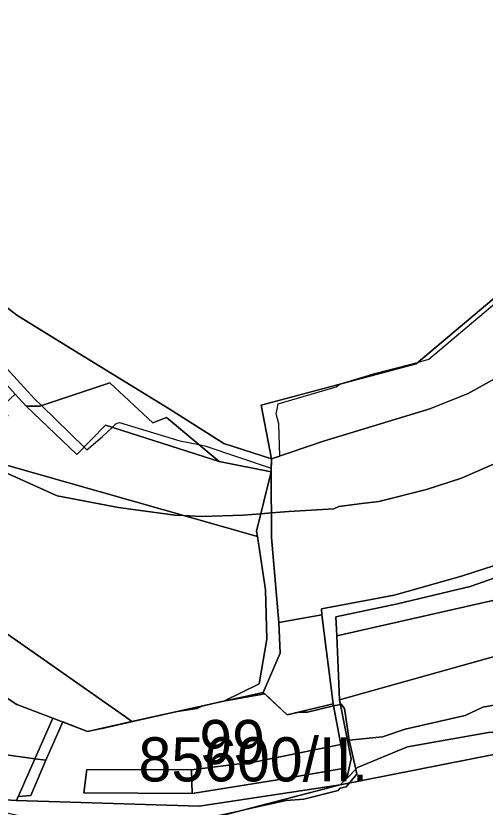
# Model space of a CAD drawing. Extents: x -477304 to -465429, y -1159113 to -1149210.
# Drawn here: x -473959.8 to -473800.3, y -1153877.8 to -1153608.7 of the extents above; entities that cross this region are included whole.
import ezdxf

# ---------------------------------------------------------------- set-up
doc = ezdxf.new("R2010")
doc.units = 0
for name, color, linetype in [('BPEJ_s', 7, 'Continuous'), ('orna_s', 7, 'Continuous'), ('ostatni_s', 7, 'Continuous'), ('PUPFL_s', 7, 'Continuous'), ('trav_porost_s', 7, 'Continuous'), ('voda_s', 7, 'Continuous')]:
    doc.layers.add(name, color=color, linetype=linetype)

msp = doc.modelspace()

# ---------------------------------------------------------------- linework, layer by layer
at = {"layer": 'BPEJ_s'}
for points in [[(-473967.96, -1153723.18), (-473959.43, -1153732.47), (-473953.5, -1153738.93), (-473951.09, -1153741.27), (-473936.66, -1153755.34), (-473935.67, -1153756.31), (-473930.51, -1153751.91), (-473927.13, -1153748.68), (-473925.83, -1153747.44), (-473925.36, -1153747.28), (-473924.56, -1153747.01), (-473904.13, -1153753.18), (-473897.7, -1153754.47), (-473895.62, -1153754.89), (-473873.03, -1153762.49), (-473872.95, -1153759.4), (-473870.13, -1153758.43), (-473870.51, -1153747.44), (-473871.36, -1153744.03), (-473871.08, -1153742.51), (-473870.73, -1153740.63), (-473850.94, -1153734.88), (-473849.68, -1153733.99), (-473849.45, -1153733.82), (-473837.53, -1153730.2), (-473823.02, -1153726.45), (-473819.44, -1153725.52), (-473739.32, -1153657.8)], [(-473967.96, -1153723.18), (-473959.43, -1153732.47), (-473953.5, -1153738.93), (-473951.09, -1153741.27), (-473936.66, -1153755.34), (-473935.67, -1153756.31), (-473930.51, -1153751.91), (-473927.13, -1153748.68), (-473925.83, -1153747.44), (-473925.36, -1153747.28), (-473924.56, -1153747.01), (-473904.13, -1153753.18), (-473897.7, -1153754.47), (-473895.62, -1153754.89), (-473873.03, -1153762.49), (-473872.95, -1153759.4), (-473870.13, -1153758.43), (-473870.51, -1153747.44), (-473871.36, -1153744.03), (-473871.08, -1153742.51), (-473870.73, -1153740.63), (-473850.94, -1153734.88), (-473849.68, -1153733.99), (-473849.45, -1153733.82), (-473837.53, -1153730.2), (-473823.02, -1153726.45), (-473819.44, -1153725.52), (-473739.32, -1153657.8)], [(-473964.14, -1153763.61), (-473945.83, -1153771.91), (-473924.98, -1153775.95), (-473905.83, -1153778.5), (-473902.9, -1153778.64), (-473896.9, -1153778.93), (-473882.43, -1153778.5), (-473879.67, -1153778.29), (-473876.56, -1153778.05), (-473872.98, -1153777.77), (-473867.1, -1153777.31), (-473851.79, -1153776.38), (-473850.08, -1153775.53), (-473842.21, -1153774.54), (-473836.47, -1153773.82), (-473820.3, -1153769.78), (-473808.38, -1153765.95), (-473793.91, -1153759.57)], [(-473793.91, -1153759.57), (-473808.38, -1153765.95), (-473820.3, -1153769.78), (-473836.47, -1153773.82), (-473842.21, -1153774.54), (-473850.08, -1153775.53), (-473851.79, -1153776.38)], [(-473851.79, -1153776.38), (-473867.1, -1153777.31), (-473872.98, -1153777.77), (-473876.56, -1153778.05), (-473879.67, -1153778.29), (-473882.43, -1153778.5), (-473896.9, -1153778.93), (-473902.9, -1153778.64), (-473905.83, -1153778.5), (-473924.98, -1153775.95), (-473945.83, -1153771.91), (-473964.14, -1153763.61)], [(-473967.25, -1153875.08), (-473959.66, -1153875.49), (-473959.05, -1153874.12), (-473954.77, -1153873.83), (-473949.68, -1153861.86), (-473943.89, -1153848.82), (-473935.5, -1153852.08), (-473930.68, -1153851), (-473930.51, -1153851.06), (-473919.6, -1153848.53), (-473905.06, -1153845.29), (-473898.17, -1153844.25), (-473896.61, -1153843.4), (-473889.84, -1153841.89), (-473875.22, -1153839.25), (-473867.59, -1153846.4), (-473863.58, -1153845.45), (-473863.49, -1153845.53), (-473860.73, -1153845.53), (-473851.84, -1153843.39), (-473849.54, -1153842.84), (-473849.23, -1153842.76), (-473848.17, -1153844.25), (-473846.61, -1153855), (-473844.32, -1153864.85), (-473843.91, -1153866.59), (-473846.43, -1153869.56), (-473847.53, -1153870.85), (-473849.66, -1153871.28), (-473850.3, -1153872.13), (-473862, -1153875.11), (-473867.96, -1153875.53), (-473881.33, -1153878.43)], [(-473796.87, -1153843.04), (-473801.15, -1153843.83), (-473807.1, -1153846.59), (-473827.53, -1153851.27), (-473835.19, -1153853.83), (-473846.61, -1153855), (-473848.17, -1153844.25), (-473849.23, -1153842.76), (-473849.54, -1153842.84), (-473851.84, -1153843.39), (-473860.73, -1153845.53), (-473863.49, -1153845.53), (-473863.58, -1153845.45), (-473867.59, -1153846.4), (-473875.22, -1153839.25), (-473889.84, -1153841.89), (-473896.61, -1153843.4), (-473898.17, -1153844.25), (-473905.06, -1153845.29), (-473919.6, -1153848.53), (-473930.51, -1153851.06), (-473930.68, -1153851), (-473935.5, -1153852.08), (-473943.89, -1153848.82), (-473949.68, -1153861.86), (-473953.37, -1153861.35)], [(-473966.69, -1153877.87), (-473964.35, -1153879.36), (-473957.75, -1153880.85), (-473923.19, -1153886.61), (-473920.73, -1153887.02), (-473903.55, -1153883.68), (-473897.75, -1153882.55), (-473893.49, -1153881.06), (-473881.33, -1153878.43), (-473867.96, -1153875.53), (-473862, -1153875.11), (-473850.3, -1153872.13), (-473849.66, -1153871.28), (-473847.53, -1153870.85), (-473846.43, -1153869.56), (-473843.91, -1153866.59), (-473844.32, -1153864.85), (-473846.61, -1153855), (-473835.19, -1153853.83), (-473827.53, -1153851.27), (-473807.1, -1153846.59), (-473801.15, -1153843.83), (-473796.87, -1153843.04)], [(-473964.56, -1153859.79), (-473953.37, -1153861.35), (-473949.68, -1153861.86), (-473954.77, -1153873.83), (-473959.05, -1153874.12), (-473959.66, -1153875.49), (-473967.25, -1153875.08)], [(-473953.37, -1153861.35), (-473964.56, -1153859.79)]]:
    msp.add_lwpolyline(points, dxfattribs=at)
for points in [[(-473900.2, -1153865.12), (-473935.72, -1153864.98), (-473936.76, -1153872.87), (-473899.93, -1153873.1)], [(-473900.2, -1153865.12), (-473899.93, -1153873.1), (-473936.76, -1153872.87), (-473935.72, -1153864.98)]]:
    msp.add_lwpolyline(points, close=True, dxfattribs=at)
at = {"layer": 'orna_s'}
for points in [[(-473796.82, -1153826.45), (-473849.84, -1153841.35), (-473850.8, -1153819.57), (-473689.77, -1153783.02), (-473686.13, -1153800.96), (-473746.01, -1153814.46), (-473777.12, -1153820.91)], [(-473899.93, -1153873.1), (-473936.76, -1153872.87), (-473935.72, -1153864.98), (-473900.2, -1153865.12)]]:
    msp.add_lwpolyline(points, close=True, dxfattribs=at)
at = {"layer": 'ostatni_s'}
for points in [[(-473873.06, -1153763.83), (-473872.93, -1153786.05), (-473870.49, -1153815.01), (-473870.05, -1153825.46), (-473875.75, -1153838.75), (-473889.11, -1153841.73), (-473877.16, -1153835.89), (-473874.54, -1153820.69), (-473875.04, -1153803.95), (-473877.74, -1153785.82), (-473878.02, -1153783.97)], [(-473847.35, -1153868.02), (-473847.98, -1153864.55), (-473849.44, -1153856.54), (-473851.97, -1153842.69), (-473855.82, -1153812.4), (-473855.95, -1153810.35), (-473831.3, -1153805.72), (-473808.33, -1153799.28), (-473750.81, -1153780.66), (-473725.74, -1153775.26), (-473763.73, -1153788.17), (-473805.39, -1153802.8), (-473830.09, -1153808.7), (-473851.08, -1153813.13), (-473850.8, -1153819.57), (-473849.84, -1153841.35), (-473845.83, -1153861.37)], [(-473843.76, -1153864.26), (-473847.35, -1153868.02), (-473845.83, -1153861.37), (-473849.84, -1153841.35), (-473796.82, -1153826.45), (-473796.9, -1153852.26), (-473799.19, -1153852.44), (-473826.7, -1153857.24)]]:
    msp.add_lwpolyline(points, close=True, dxfattribs=at)
at = {"layer": 'PUPFL_s'}
for points in [[(-473317.9, -1153181.74), (-473336.03, -1153216.76), (-473345.77, -1153242.45), (-473360.35, -1153318.85), (-473425.22, -1153434.63), (-473427.02, -1153440.19), (-473427.69, -1153442.92), (-473433.83, -1153466.27), (-473506.84, -1153474.05), (-473574.91, -1153481.82), (-473579.34, -1153482.33), (-473644.06, -1153489.73), (-473629.89, -1153542.49), (-473625.46, -1153559), (-473742.33, -1153616.45), (-473722.79, -1153641.99), (-473823.78, -1153727.09), (-473876.42, -1153741.11), (-473872.95, -1153759.4), (-473889.2, -1153754.19), (-473907.69, -1153742.41)], [(-473907.69, -1153742.41), (-473941.13, -1153721.8), (-473959.5, -1153710.48), (-473978.64, -1153695.63), (-473993.79, -1153702.69), (-473996.1, -1153703.76), (-474005.41, -1153685.4), (-474007.19, -1153681.89), (-474013.18, -1153684.64), (-474018.73, -1153672.6), (-473996.2, -1153665.65), (-473985.18, -1153667.66), (-473992.8, -1153643.11), (-473991.36, -1153629.33), (-473995.72, -1153606.47)]]:
    msp.add_lwpolyline(points, dxfattribs=at)
for points in [[(-473772.87, -1153717.61), (-473781.67, -1153723.51), (-473806.16, -1153737.16), (-473819.14, -1153742.37), (-473855.33, -1153753.34), (-473872.95, -1153759.4), (-473876.42, -1153741.11), (-473823.78, -1153727.09), (-473722.79, -1153641.99), (-473716.48, -1153650.25), (-473736.96, -1153677.1), (-473743.44, -1153686.38), (-473757.62, -1153702.35), (-473759.18, -1153703.96), (-473765.34, -1153710.29)], [(-473908.69, -1153745.3), (-473913.25, -1153747.06), (-473927.95, -1153733.48), (-473951.66, -1153741.46), (-473956.35, -1153741.42), (-473960.03, -1153737.37), (-473978.12, -1153717.47), (-473993.79, -1153702.69), (-473978.64, -1153695.63), (-473959.5, -1153710.48), (-473941.13, -1153721.8), (-473907.69, -1153742.41), (-473889.2, -1153754.19), (-473872.95, -1153759.4), (-473873.06, -1153763.83), (-473890.75, -1153760.27)], [(-473956.35, -1153741.42), (-473951.66, -1153741.46), (-473927.95, -1153733.48), (-473913.25, -1153747.06), (-473908.69, -1153745.3), (-473890.75, -1153760.27), (-473929.39, -1153747.96), (-473939.17, -1153757.88)], [(-473956.35, -1153741.42), (-473939.17, -1153757.88), (-473929.39, -1153747.96), (-473890.75, -1153760.27), (-473873.06, -1153763.83), (-473878.02, -1153783.97), (-473877.74, -1153785.82), (-473974.69, -1153758.17), (-473962.43, -1153744.64), (-473965.18, -1153742.09), (-473960.03, -1153737.37)], [(-473847.35, -1153868.02), (-473849.63, -1153870.19), (-473897.54, -1153877.44), (-473959.66, -1153875.49), (-473947.22, -1153847.53), (-473935.5, -1153852.08), (-473920.46, -1153848.72), (-473889.11, -1153841.73), (-473875.75, -1153838.75), (-473867.59, -1153846.4), (-473851.97, -1153842.69), (-473849.44, -1153856.54), (-473878.42, -1153862.41), (-473900.2, -1153865.12), (-473935.72, -1153864.98), (-473936.76, -1153872.87), (-473899.93, -1153873.1), (-473870.26, -1153868.41), (-473847.98, -1153864.55)], [(-473878.42, -1153862.41), (-473849.44, -1153856.54), (-473847.98, -1153864.55), (-473870.26, -1153868.41), (-473899.93, -1153873.1), (-473900.2, -1153865.12)], [(-473898.84, -1153882.98), (-473926.07, -1153887.04), (-473960.25, -1153882.89), (-473969.67, -1153880.22), (-473973.05, -1153874.77), (-473959.66, -1153875.49), (-473897.54, -1153877.44), (-473849.63, -1153870.19)]]:
    msp.add_lwpolyline(points, close=True, dxfattribs=at)
at = {"layer": 'trav_porost_s'}
for points in [[(-473855.82, -1153812.4), (-473870.49, -1153815.01), (-473872.93, -1153786.05), (-473873.06, -1153763.83), (-473872.95, -1153759.4), (-473855.33, -1153753.34), (-473819.14, -1153742.37), (-473806.16, -1153737.16), (-473781.67, -1153723.51), (-473772.87, -1153717.61), (-473701.8, -1153768.21), (-473725.74, -1153775.26), (-473750.81, -1153780.66), (-473808.33, -1153799.28), (-473831.3, -1153805.72), (-473855.95, -1153810.35)], [(-473922.62, -1153847.07), (-474011.57, -1153784.78), (-473979, -1153755.56), (-473974.69, -1153758.17), (-473877.74, -1153785.82), (-473875.04, -1153803.95), (-473874.54, -1153820.69), (-473877.16, -1153835.89), (-473889.11, -1153841.73), (-473920.46, -1153848.72)], [(-473667.02, -1153786.39), (-473673.22, -1153788.66), (-473676.41, -1153789.83), (-473675.42, -1153792.54), (-473674.73, -1153794.41), (-473671.37, -1153793.18), (-473669.96, -1153797.32), (-473686.13, -1153800.96), (-473689.77, -1153783.02), (-473850.8, -1153819.57), (-473851.08, -1153813.13), (-473830.09, -1153808.7), (-473805.39, -1153802.8), (-473763.73, -1153788.17), (-473725.74, -1153775.26), (-473701.8, -1153768.21), (-473676.23, -1153761.51), (-473667.78, -1153778.92)], [(-473935.5, -1153852.08), (-473947.22, -1153847.53), (-473959.45, -1153842.89), (-473973.61, -1153833.55), (-473977.75, -1153824.58), (-473986.64, -1153821.6), (-474007.78, -1153822.76), (-474003.88, -1153815.35), (-474001.83, -1153805.97), (-474001.56, -1153801.92), (-474015.4, -1153793.35), (-474011.57, -1153784.78), (-473922.62, -1153847.07), (-473920.46, -1153848.72)], [(-473870.05, -1153825.46), (-473870.49, -1153815.01), (-473855.82, -1153812.4), (-473851.97, -1153842.69), (-473867.59, -1153846.4), (-473875.75, -1153838.75)], [(-473947.22, -1153847.53), (-473959.66, -1153875.49), (-473973.05, -1153874.77), (-473978.88, -1153863.97), (-473971.17, -1153852.83), (-473986.97, -1153840.23), (-473995.81, -1153830.53), (-474012.45, -1153823.5), (-474007.78, -1153822.76), (-473986.64, -1153821.6), (-473977.75, -1153824.58), (-473973.61, -1153833.55), (-473959.45, -1153842.89)]]:
    msp.add_lwpolyline(points, close=True, dxfattribs=at)
at = {"layer": 'voda_s'}
msp.add_lwpolyline([(-473788.82, -1153858.15), (-473849.63, -1153870.19), (-473847.35, -1153868.02), (-473843.76, -1153864.26), (-473826.7, -1153857.24), (-473799.19, -1153852.44), (-473796.9, -1153852.26), (-473770.58, -1153850.14), (-473770.29, -1153851.19), (-473747.94, -1153853.1)], close=True, dxfattribs=at)
msp.add_lwpolyline([(-474303.54, -1153897.14), (-474290.58, -1153895.88), (-474227.94, -1153885.74), (-474202.37, -1153879.94), (-474165.39, -1153867.04), (-474084.14, -1153854.43), (-474075.98, -1153856.54), (-474082.42, -1153862.08), (-474032.41, -1153869.61), (-474028.31, -1153870.23), (-474021.95, -1153871.19), (-473994.36, -1153873.21), (-473969.67, -1153880.22), (-473960.25, -1153882.89), (-473926.07, -1153887.04), (-473898.84, -1153882.98), (-473849.63, -1153870.19), (-473788.82, -1153858.15)], dxfattribs=at)

# ---------------------------------------------------------------- texts
at = {"layer": 'BPEJ_s'}
for s, p in [('99', (-473897.47, -1153863.14)), ('85600/II.', (-473918.16, -1153869.04))]:
    msp.add_text(s, height=15, dxfattribs=at).set_placement(p)

doc.saveas('drawing.dxf')
